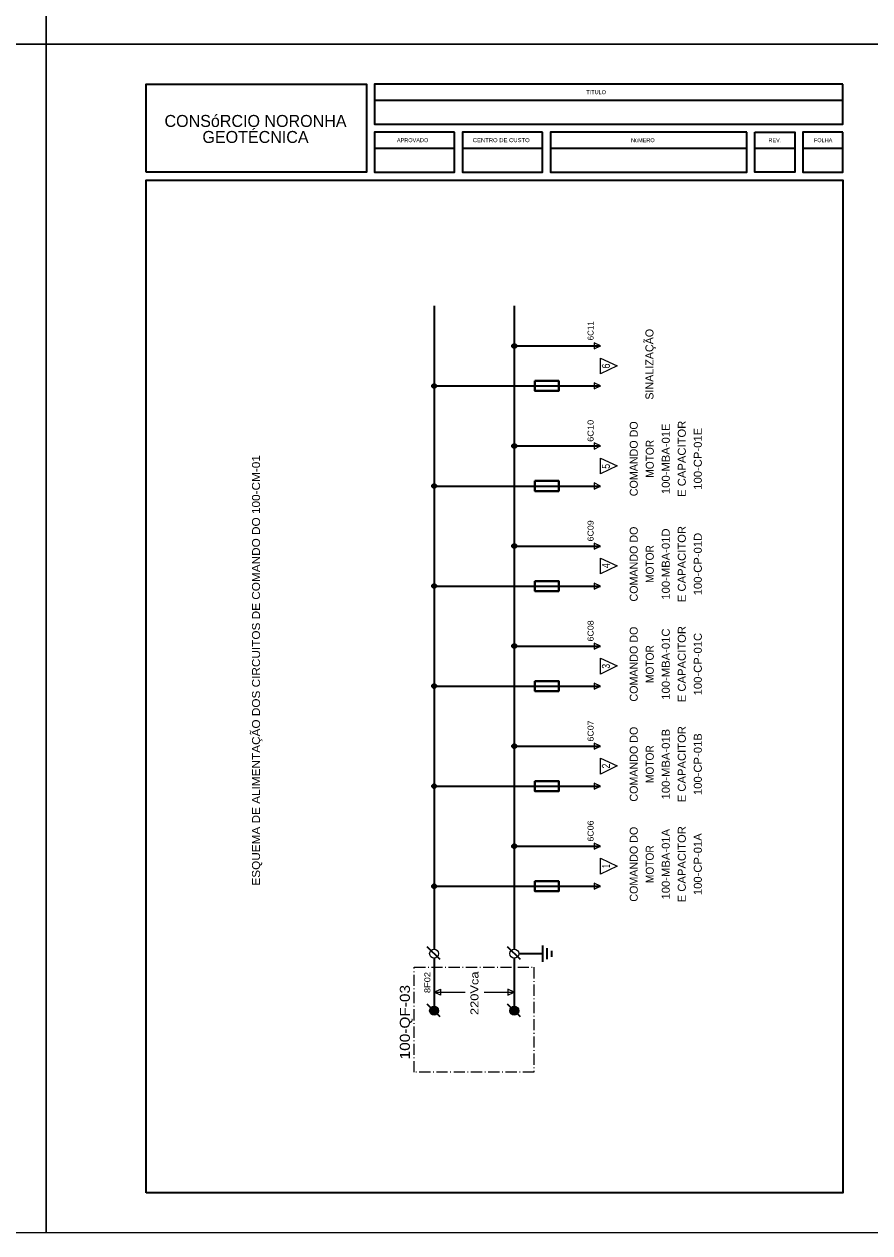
# Model space of a CAD drawing. Extents: x -4160 to -2690, y -474 to 714.
# Drawn here: x -3115.3 to -2904, y -473.5 to -171.5 of the extents above; entities that cross this region are included whole.
import ezdxf
from ezdxf.enums import TextEntityAlignment as Align

# ---------------------------------------------------------------- set-up
doc = ezdxf.new("R2010")
doc.units = 0
doc.header["$LTSCALE"] = 0.56
doc.linetypes.add('DOT_DASHED', pattern=[7.7, 5, -1.2, 0.3, -1.2])
doc.layers.add('2', color=7, linetype='Continuous', lineweight=25)
doc.layers.add('5', color=7, linetype='Continuous', lineweight=35)

msp = doc.modelspace()

# ---------------------------------------------------------------- hatches: boundary and pattern name
at = {"layer": '2'}
for points in [[(-2992.8515, -251.3999, 1), (-2992.8515, -252.4313, 1)], [(-3012.8515, -261.3999, 1), (-3012.8515, -262.4313, 1)], [(-2992.8515, -276.3999, 1), (-2992.8515, -277.4313, 1)], [(-3012.8515, -286.3999, 1), (-3012.8515, -287.4313, 1)], [(-2992.8515, -301.3999, 1), (-2992.8515, -302.4313, 1)], [(-3012.8515, -311.3999, 1), (-3012.8515, -312.4313, 1)], [(-2992.8515, -326.3999, 1), (-2992.8515, -327.4313, 1)], [(-3012.8515, -336.3999, 1), (-3012.8515, -337.4313, 1)], [(-2992.8515, -351.3999, 1), (-2992.8515, -352.4313, 1)], [(-3012.8515, -361.3999, 1), (-3012.8515, -362.4313, 1)], [(-2992.8515, -376.3999, 1), (-2992.8515, -377.4313, 1)], [(-3012.8515, -386.3999, 1), (-3012.8515, -387.4313, 1)], [(-3012.8515, -419.1497, 1), (-3012.8515, -416.9019, 1)], [(-2992.8515, -419.1497, 1), (-2992.8515, -416.9019, 1)]]:
    msp.add_hatch(color=256, dxfattribs=at).paths.add_polyline_path(points)

# ---------------------------------------------------------------- linework, layer by layer
at = {"layer": '2', "lineweight": 35}
for p, q in [((-3012.8515, -241.9156), (-3012.8515, -402.6255)), ((-2992.8515, -241.9156), (-2992.8515, -402.6255)), ((-2992.8515, -251.9156), (-2971.2866, -251.9156)), ((-3012.8515, -261.9156), (-2971.2866, -261.9156)), ((-2992.8515, -276.9156), (-2971.2866, -276.9156)), ((-3012.8515, -286.9156), (-2971.2866, -286.9156)), ((-2992.8515, -301.9156), (-2971.2866, -301.9156)), ((-3012.8515, -311.9156), (-2971.2866, -311.9156)), ((-2992.8515, -326.9156), (-2971.2866, -326.9156)), ((-3012.8515, -336.9156), (-2971.2866, -336.9156)), ((-2992.8515, -351.9156), (-2971.2866, -351.9156)), ((-3012.8515, -361.9156), (-2971.2866, -361.9156)), ((-2992.8515, -376.9156), (-2971.2866, -376.9156)), ((-2992.8515, -376.9156), (-2971.2866, -376.9156)), ((-3012.8515, -386.9156), (-2971.2866, -386.9156)), ((-3014.6426, -402.0101), (-3011.3965, -405.1573)), ((-2994.6426, -402.0101), (-2991.3965, -405.1573)), ((-2991.7276, -403.7494), (-2985.6803, -403.7494)), ((-2985.6803, -405.8102), (-2985.6803, -401.6885)), ((-2984.579, -405.1802), (-2984.579, -402.3937)), ((-2983.4198, -404.5416), (-2983.4198, -403.0322)), ((-3012.8515, -404.8733), (-3012.8515, -416.9019)), ((-2992.8515, -404.8733), (-2992.8515, -416.9019)), ((-3014.6426, -416.2865), (-3011.3965, -419.4337)), ((-2994.6426, -416.2865), (-2991.3965, -419.4337))]:
    msp.add_line(p, q, dxfattribs=at)
at = {"layer": '2'}
for p, q in [((-3012.8515, -413.3876), (-3005.1265, -413.3876)), ((-3000.3738, -413.3876), (-2992.8515, -413.3876))]:
    msp.add_line(p, q, dxfattribs=at)
for points in [[(-2972.8776, -251.1598), (-2972.8776, -252.6715), (-2971.2866, -251.9156)], [(-2971.2866, -258.8995), (-2971.2866, -254.9317), (-2967.1435, -256.8702)], [(-2972.8776, -261.1598), (-2972.8776, -262.6715), (-2971.2866, -261.9156)], [(-2972.8776, -276.1598), (-2972.8776, -277.6715), (-2971.2866, -276.9156)], [(-2971.2866, -283.8995), (-2971.2866, -279.9317), (-2967.1435, -281.8702)], [(-2972.8776, -286.1598), (-2972.8776, -287.6715), (-2971.2866, -286.9156)], [(-2972.8776, -301.1598), (-2972.8776, -302.6715), (-2971.2866, -301.9156)], [(-2971.2866, -308.8995), (-2971.2866, -304.9317), (-2967.1435, -306.8702)], [(-2972.8776, -311.1598), (-2972.8776, -312.6715), (-2971.2866, -311.9156)], [(-2972.8776, -326.1598), (-2972.8776, -327.6715), (-2971.2866, -326.9156)], [(-2971.2866, -333.8995), (-2971.2866, -329.9317), (-2967.1435, -331.8702)], [(-2972.8776, -336.1598), (-2972.8776, -337.6715), (-2971.2866, -336.9156)], [(-2972.8776, -351.1598), (-2972.8776, -352.6715), (-2971.2866, -351.9156)], [(-2971.2866, -358.8995), (-2971.2866, -354.9317), (-2967.1435, -356.8702)], [(-2972.8776, -361.1598), (-2972.8776, -362.6715), (-2971.2866, -361.9156)], [(-2972.8776, -376.1598), (-2972.8776, -377.6715), (-2971.2866, -376.9156)], [(-2971.2866, -383.8995), (-2971.2866, -379.9317), (-2967.1435, -381.8702)], [(-2972.8776, -386.1598), (-2972.8776, -387.6715), (-2971.2866, -386.9156)], [(-3011.2605, -412.6318), (-3011.2605, -414.1435), (-3012.8515, -413.3876)], [(-2994.4425, -412.6318), (-2994.4425, -414.1435), (-2992.8515, -413.3876)]]:
    msp.add_lwpolyline(points, close=True, dxfattribs=at)
at = {"layer": '2', "lineweight": 40}
for points in [[(-2987.6813, -260.6559), (-2981.7055, -260.6559), (-2981.7055, -263.1753), (-2987.6813, -263.1753)], [(-2987.6813, -285.6559), (-2981.7055, -285.6559), (-2981.7055, -288.1753), (-2987.6813, -288.1753)], [(-2987.6813, -310.6559), (-2981.7055, -310.6559), (-2981.7055, -313.1753), (-2987.6813, -313.1753)], [(-2987.6813, -335.6559), (-2981.7055, -335.6559), (-2981.7055, -338.1753), (-2987.6813, -338.1753)], [(-2987.6813, -360.6559), (-2981.7055, -360.6559), (-2981.7055, -363.1753), (-2987.6813, -363.1753)], [(-2987.6813, -385.6559), (-2981.7055, -385.6559), (-2981.7055, -388.1753), (-2987.6813, -388.1753)]]:
    msp.add_lwpolyline(points, close=True, dxfattribs=at)
at = {"layer": '2', "linetype": 'DOT_DASHED'}
msp.add_lwpolyline([(-3017.8515, -433.3876), (-3017.8515, -407.1813), (-2987.9261, -407.1813), (-2987.9261, -433.3876)], close=True, dxfattribs=at)
at = {"layer": '2', "lineweight": 35}
for centre in [(-2992.8515, -251.9156), (-3012.8515, -261.9156), (-2992.8515, -276.9156), (-3012.8515, -286.9156), (-2992.8515, -301.9156), (-3012.8515, -311.9156), (-2992.8515, -326.9156), (-3012.8515, -336.9156), (-2992.8515, -351.9156), (-3012.8515, -361.9156), (-2992.8515, -376.9156), (-3012.8515, -386.9156)]:
    msp.add_circle(centre, 0.5157, dxfattribs=at)
at = {"layer": '2'}
for centre in [(-3012.8515, -403.7494), (-2992.8515, -403.7494), (-3012.8515, -418.0258), (-2992.8515, -418.0258)]:
    msp.add_circle(centre, 1.1239, dxfattribs=at)
at = {"layer": '5'}
for p, q in [((-3027.7642, -190.52), (-2910.7642, -190.52)), ((-3027.7642, -202.52), (-3007.7642, -202.52)), ((-3005.7642, -202.52), (-2985.7642, -202.52)), ((-2983.7642, -202.52), (-2934.7642, -202.52)), ((-2932.7642, -202.52), (-2922.7642, -202.52)), ((-2920.7642, -202.52), (-2910.7642, -202.52))]:
    msp.add_line(p, q, dxfattribs=at)
at = {"layer": '5', "lineweight": 25}
for points in [[(-3109.7642, -176.52), (-3319.7642, -176.52), (-3319.7642, 120.48), (-3109.7642, 120.48)], [(-2899.7642, -176.52), (-3109.7642, -176.52), (-3109.7642, 120.48), (-2899.7642, 120.48)], [(-3109.7642, -473.52), (-3319.7642, -473.52), (-3319.7642, -176.52), (-3109.7642, -176.52)], [(-2899.7642, -473.52), (-3109.7642, -473.52), (-3109.7642, -176.52), (-2899.7642, -176.52)]]:
    msp.add_lwpolyline(points, close=True, dxfattribs=at)
at = {"layer": '5'}
for points in [[(-3084.7642, -208.52), (-3084.7642, -186.52), (-3029.7642, -186.52), (-3029.7642, -208.52)], [(-2910.7642, -186.52), (-3027.7642, -186.52), (-3027.7642, -196.52), (-2910.7642, -196.52)], [(-3007.7642, -198.52), (-3027.7642, -198.52), (-3027.7642, -208.52), (-3007.7642, -208.52)], [(-2985.7642, -198.52), (-3005.7642, -198.52), (-3005.7642, -208.52), (-2985.7642, -208.52)], [(-2934.7642, -198.52), (-2983.7642, -198.52), (-2983.7642, -208.52), (-2934.7642, -208.52)], [(-2932.7642, -198.52), (-2922.7642, -198.52), (-2922.7642, -208.52), (-2932.7642, -208.52)], [(-2910.7642, -198.52), (-2920.7642, -198.52), (-2920.7642, -208.52), (-2910.7642, -208.52)], [(-3084.7642, -463.52), (-3084.7642, -210.52), (-2910.7642, -210.52), (-2910.7642, -463.52)]]:
    msp.add_lwpolyline(points, close=True, dxfattribs=at)

# ---------------------------------------------------------------- texts
at = {"layer": '2'}
for s, height, p in [('6C11', 1.5, (-2973.0311, -248.1233)), ('SINALIZAÇÃO', 2, (-2958.0662, -256.4975)), ('COMANDO DO', 2, (-2961.9909, -280.1114)), ('COMANDO DO', 2, (-2961.9909, -306.4172)), ('COMANDO DO', 2, (-2961.9909, -331.4172)), ('COMANDO DO', 2, (-2961.9909, -356.4172)), ('COMANDO DO', 2, (-2961.9909, -381.4172))]:
    msp.add_text(s, height=height, rotation=90, dxfattribs=at).set_placement(p, align=Align.CENTER)
for s, height, width, p in [('6', 2, 0.85, (-2968.9434, -256.9455)), ('6C10', 1.5, 1.15, (-2973.0311, -273.1234)), ('100-MBA-01E', 2, 1.05, (-2953.9909, -280.1114)), ('E CAPACITOR', 2, 1.05, (-2949.9909, -280.1114)), ('100-CP-01E', 2, 1.05, (-2945.9909, -280.1114)), ('MOTOR', 2, 0.95, (-2957.9909, -280.1114)), ('ESQUEMA DE ALIMENTAÇÃO DOS CIRCUITOS DE COMANDO DO 100-CM-01', 2, 1.1, (-3056.3493, -332.9804)), ('5', 2, 0.8, (-2968.9434, -282.0018)), ('6C09', 1.5, 1.1, (-2973.0311, -298.1233)), ('100-MBA-01D', 2, 1.05, (-2953.9909, -306.4171)), ('E CAPACITOR', 2, 1.05, (-2949.9909, -306.4172)), ('100-CP-01D', 2, 1.05, (-2945.9909, -306.4172)), ('MOTOR', 2, 0.95, (-2957.9909, -306.4171)), ('4', 2, 0.8, (-2968.9434, -306.8324)), ('6C08', 1.5, 1.1, (-2973.0311, -323.1233)), ('100-MBA-01C', 2, 1.05, (-2953.9909, -331.4171)), ('E CAPACITOR', 2, 1.05, (-2949.9909, -331.4172)), ('100-CP-01C', 2, 1.05, (-2945.9909, -331.4172)), ('MOTOR', 2, 0.95, (-2957.9909, -331.4171)), ('3', 2, 0.8, (-2968.9434, -331.9479)), ('6C07', 1.5, 1.1, (-2973.0311, -348.1233)), ('E CAPACITOR', 2, 1.05, (-2949.9909, -356.4172)), ('100-MBA-01B', 2, 1.05, (-2953.9909, -356.4171)), ('100-CP-01B', 2, 1.05, (-2945.9909, -356.4172)), ('MOTOR', 2, 0.95, (-2957.9909, -356.4171)), ('2', 2, 0.8, (-2968.9434, -356.8891)), ('6C06', 1.5, 1.1, (-2973.0311, -373.1233)), ('100-MBA-01A', 2, 1.05, (-2953.9909, -381.4173)), ('E CAPACITOR', 2, 1.05, (-2949.9909, -381.4172)), ('100-CP-01A', 2, 1.05, (-2945.9909, -381.4172)), ('MOTOR', 2, 0.95, (-2957.9909, -381.4171)), ('1', 2, 0.45, (-2968.9434, -381.8891)), ('8F02', 1.5, 1.15, (-3013.7961, -410.9831)), ('220Vca', 2, 1.2, (-3001.7792, -413.6601)), ('100-QF-03', 2.5, 1.15, (-3018.9169, -420.888))]:
    msp.add_text(s, height=height, rotation=90, dxfattribs=dict(at, width=width)).set_placement(p, align=Align.CENTER)
at = {"layer": '5'}
for s, height, p in [('TíTULO', 1, (-2972.3847, -189.009)), ('CONSóRCIO NORONHA', 3, (-3057.4749, -197.2039)), ('GEOTÉCNICA', 3, (-3057.475, -201.2039)), ('APROVADO', 1, (-3018.2387, -201.0027)), ('REV.', 1, (-2927.7443, -201.0077)), ('FOLHA', 1, (-2915.6809, -201.0077))]:
    msp.add_text(s, height=height, dxfattribs=at).set_placement(p, align=Align.CENTER)
for s, width, p in [('CENTRO DE CUSTO', 1.1, (-2996.0934, -201.0027)), ('NúMERO', 0.95, (-2960.7228, -201.0077))]:
    msp.add_text(s, height=1, dxfattribs=dict(at, width=width)).set_placement(p, align=Align.CENTER)

doc.saveas('drawing.dxf')
